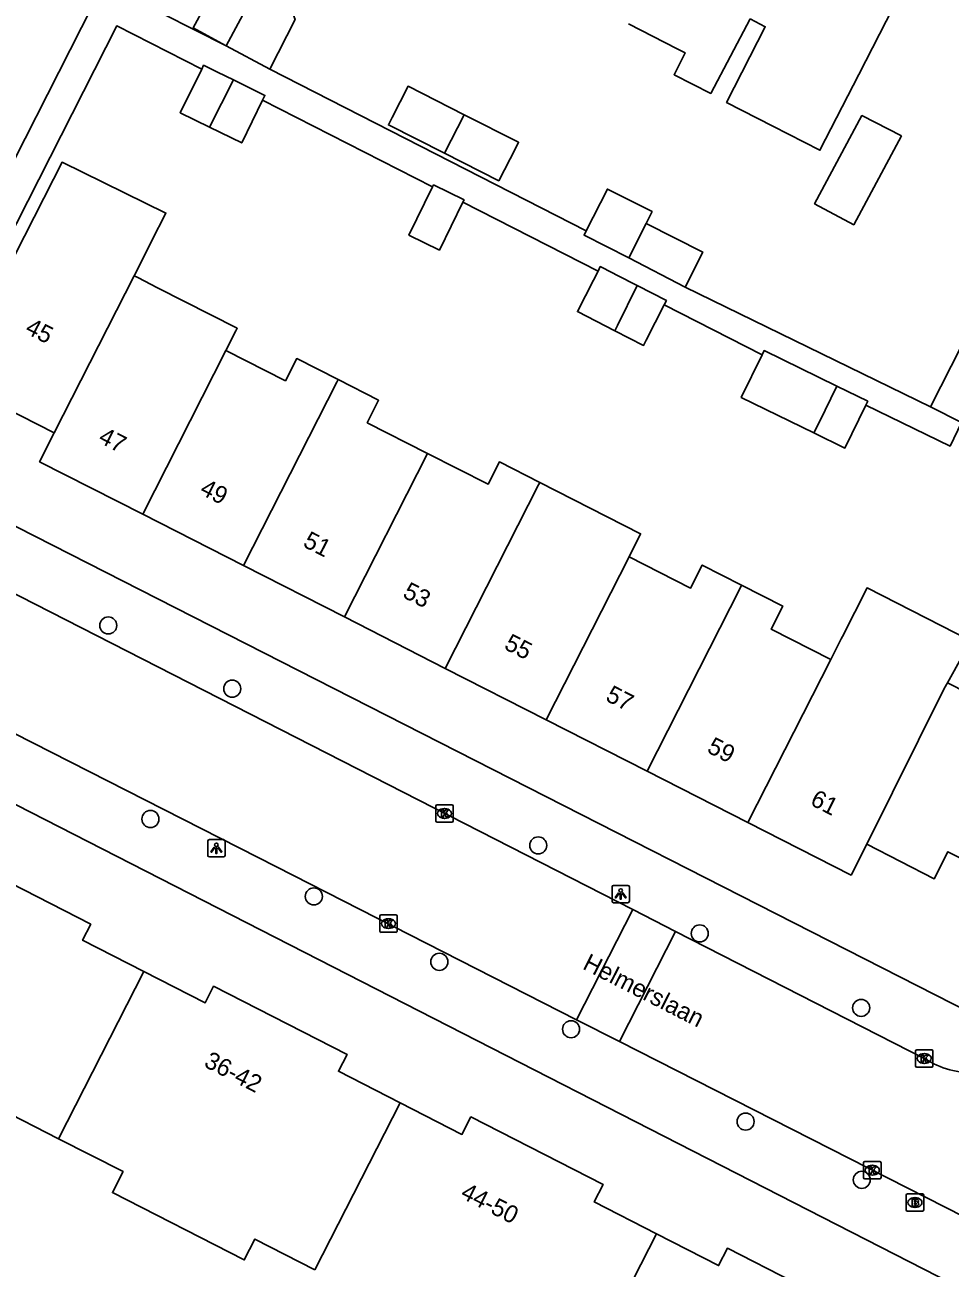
# Model space of a CAD drawing. Extents: x 160356 to 161355, y 381727 to 382845.
# Drawn here: x 161066.7 to 161119.7, y 382327 to 382398.2 of the extents above; entities that cross this region are included whole.
import ezdxf

# ---------------------------------------------------------------- set-up
doc = ezdxf.new("R2010")
doc.units = 0
for name, color, linetype in [('IMGEO_Boom', 7, 'Continuous'), ('IMGEO_Brandkraan', 7, 'Continuous'), ('IMGEO_Kolk', 7, 'Continuous'), ('IMGEO_Lichtpunt', 7, 'Continuous'), ('IMGEO_Openbare_ruimte_label', 7, 'Continuous'), ('IMGEO_Pand', 7, 'Continuous'), ('IMGEO_Pand_nummerreeks', 7, 'Continuous'), ('IMGEO_Rijbaan_lokaal_open', 7, 'Continuous'), ('IMGEO_Voetpad_open', 7, 'Continuous')]:
    doc.layers.add(name, color=color, linetype=linetype)

msp = doc.modelspace()

# ---------------------------------------------------------------- linework, layer by layer
at = {"layer": 'IMGEO_Boom'}
for centre in [(161071.448, 382363.796), (161078.554, 382360.172), (161073.864, 382352.703), (161096.102, 382351.193), (161083.234, 382348.269), (161105.362, 382346.148), (161090.43, 382344.518), (161114.618, 382341.878), (161097.982, 382340.656), (161107.992, 382335.362), (161114.652, 382332.027)]:
    msp.add_circle(centre, 0.489, dxfattribs=at)
at = {"layer": 'IMGEO_Brandkraan'}
for p, q in [((161117.202, 382330.3), (161117.202, 382331.152)), ((161117.277, 382331.226), (161118.129, 382331.226)), ((161117.69, 382331.006), (161117.715, 382331.006)), ((161118.203, 382331.152), (161118.203, 382330.3)), ((161118.129, 382330.226), (161117.277, 382330.226)), ((161117.713, 382330.446), (161117.688, 382330.446))]:
    msp.add_line(p, q, dxfattribs=at)
for points in [[(161117.202, 382330.3), (161117.202, 382331.152)], [(161117.277, 382331.226), (161118.129, 382331.226)], [(161117.55, 382330.926), (161117.55, 382330.526), (161117.763, 382330.526)], [(161117.781, 382330.926), (161117.55, 382330.926)], [(161118.203, 382331.152), (161118.203, 382330.3)], [(161118.129, 382330.226), (161117.277, 382330.226)], [(161117.729, 382330.845), (161117.675, 382330.845), (161117.675, 382330.769)], [(161117.675, 382330.769), (161117.728, 382330.769)], [(161117.737, 382330.693), (161117.675, 382330.693), (161117.675, 382330.612)], [(161117.675, 382330.612), (161117.737, 382330.612)]]:
    msp.add_lwpolyline(points, dxfattribs=at)
for centre, radius, start, end in [((161117.279, 382331.15), 0.0765, 91.55205, 178.44795), ((161117.279, 382331.15), 0.0765, 91.55205, 178.44795), ((161117.785, 382330.781), 0.145, 59.4692, 91.53667), ((161117.81, 382330.828), 0.0922, 285.51372, 58.15012), ((161118.127, 382331.15), 0.0765, 1.55205, 88.44795), ((161118.127, 382331.15), 0.0765, 1.55205, 88.44795), ((161117.279, 382330.302), 0.0765, 181.55205, 268.44795), ((161117.279, 382330.302), 0.0765, 181.55205, 268.44795), ((161117.73, 382330.807), 0.0379, 267.82845, 90.93552), ((161117.738, 382330.652), 0.0404, 269.87594, 90.50774), ((161117.769, 382330.777), 0.251, 268.66757, 293.53466), ((161117.815, 382330.636), 0.105, 301.31148, 78.98903), ((161118.127, 382330.302), 0.0765, 271.55205, 358.44795), ((161118.127, 382330.302), 0.0765, 271.55205, 358.44795)]:
    msp.add_arc(centre, radius, start, end, dxfattribs=at)
for centre, major_axis, ratio, start_param, end_param in [((161117.689, 382330.726), (-0.387, 0.002), 0.722429, 4.712389, 7.853982), ((161117.714, 382330.726), (-0.39, 0.002), 0.717154, 1.570796, 4.712389)]:
    msp.add_ellipse(centre, major_axis=major_axis, ratio=ratio, start_param=start_param, end_param=end_param, dxfattribs=at)
at = {"layer": 'IMGEO_Kolk'}
for p, q in [((161090.226, 382352.596), (161090.226, 382353.448)), ((161090.301, 382353.522), (161091.153, 382353.522)), ((161090.714, 382353.302), (161090.739, 382353.302)), ((161091.227, 382353.448), (161091.227, 382352.596)), ((161091.153, 382352.522), (161090.301, 382352.522)), ((161090.737, 382352.742), (161090.712, 382352.742)), ((161087.012, 382346.284), (161087.012, 382347.136)), ((161087.087, 382347.21), (161087.939, 382347.21)), ((161087.5, 382346.99), (161087.525, 382346.99)), ((161088.013, 382347.136), (161088.013, 382346.284)), ((161087.939, 382346.21), (161087.087, 382346.21)), ((161087.523, 382346.43), (161087.498, 382346.43)), ((161117.808, 382339.478), (161118.66, 382339.478)), ((161117.733, 382338.552), (161117.733, 382339.404)), ((161118.221, 382339.258), (161118.246, 382339.258)), ((161118.734, 382339.404), (161118.734, 382338.552)), ((161118.66, 382338.478), (161117.808, 382338.478)), ((161118.244, 382338.698), (161118.219, 382338.698)), ((161114.83, 382333.078), (161115.682, 382333.078)), ((161114.755, 382332.152), (161114.755, 382333.004)), ((161115.243, 382332.858), (161115.268, 382332.858)), ((161115.756, 382333.004), (161115.756, 382332.152)), ((161115.682, 382332.078), (161114.83, 382332.078)), ((161115.266, 382332.298), (161115.241, 382332.298))]:
    msp.add_line(p, q, dxfattribs=at)
for points in [[(161090.226, 382352.596), (161090.226, 382353.448)], [(161090.301, 382353.522), (161091.153, 382353.522)], [(161090.547, 382353.222), (161090.67, 382353.222), (161090.67, 382353.071), (161090.8, 382353.222), (161090.964, 382353.222), (161090.818, 382353.071), (161090.971, 382352.822), (161090.819, 382352.822), (161090.734, 382352.986), (161090.67, 382352.919), (161090.67, 382352.822), (161090.547, 382352.822), (161090.547, 382353.222)], [(161091.227, 382353.448), (161091.227, 382352.596)], [(161091.153, 382352.522), (161090.301, 382352.522)], [(161087.012, 382346.284), (161087.012, 382347.136)], [(161087.087, 382347.21), (161087.939, 382347.21)], [(161087.333, 382346.91), (161087.456, 382346.91), (161087.456, 382346.759), (161087.586, 382346.91), (161087.75, 382346.91), (161087.604, 382346.759), (161087.757, 382346.51), (161087.605, 382346.51), (161087.52, 382346.674), (161087.456, 382346.607), (161087.456, 382346.51), (161087.333, 382346.51), (161087.333, 382346.91)], [(161088.013, 382347.136), (161088.013, 382346.284)], [(161087.939, 382346.21), (161087.087, 382346.21)], [(161117.808, 382339.478), (161118.66, 382339.478)], [(161117.733, 382338.552), (161117.733, 382339.404)], [(161118.054, 382339.178), (161118.177, 382339.178), (161118.177, 382339.027), (161118.307, 382339.178), (161118.471, 382339.178), (161118.325, 382339.027), (161118.478, 382338.778), (161118.326, 382338.778), (161118.241, 382338.942), (161118.177, 382338.875), (161118.177, 382338.778), (161118.054, 382338.778), (161118.054, 382339.178)], [(161118.734, 382339.404), (161118.734, 382338.552)], [(161118.66, 382338.478), (161117.808, 382338.478)], [(161114.83, 382333.078), (161115.682, 382333.078)], [(161114.755, 382332.152), (161114.755, 382333.004)], [(161115.076, 382332.778), (161115.199, 382332.778), (161115.199, 382332.627), (161115.329, 382332.778), (161115.493, 382332.778), (161115.347, 382332.627), (161115.5, 382332.378), (161115.348, 382332.378), (161115.263, 382332.542), (161115.199, 382332.475), (161115.199, 382332.378), (161115.076, 382332.378), (161115.076, 382332.778)], [(161115.756, 382333.004), (161115.756, 382332.152)], [(161115.682, 382332.078), (161114.83, 382332.078)]]:
    msp.add_lwpolyline(points, dxfattribs=at)
for centre, start, end in [((161090.303, 382353.446), 91.55205, 178.44795), ((161090.303, 382353.446), 91.55205, 178.44795), ((161091.151, 382353.446), 1.55205, 88.44795), ((161091.151, 382353.446), 1.55205, 88.44795), ((161090.303, 382352.598), 181.55205, 268.44795), ((161090.303, 382352.598), 181.55205, 268.44795), ((161091.151, 382352.598), 271.55205, 358.44795), ((161091.151, 382352.598), 271.55205, 358.44795), ((161087.089, 382347.134), 91.55205, 178.44795), ((161087.089, 382347.134), 91.55205, 178.44795), ((161087.937, 382347.134), 1.55205, 88.44795), ((161087.937, 382347.134), 1.55205, 88.44795), ((161087.089, 382346.286), 181.55205, 268.44795), ((161087.089, 382346.286), 181.55205, 268.44795), ((161087.937, 382346.286), 271.55205, 358.44795), ((161087.937, 382346.286), 271.55205, 358.44795), ((161117.81, 382339.402), 91.55205, 178.44795), ((161117.81, 382339.402), 91.55205, 178.44795), ((161118.658, 382339.402), 1.55205, 88.44795), ((161118.658, 382339.402), 1.55205, 88.44795), ((161117.81, 382338.554), 181.55205, 268.44795), ((161117.81, 382338.554), 181.55205, 268.44795), ((161118.658, 382338.554), 271.55205, 358.44795), ((161118.658, 382338.554), 271.55205, 358.44795), ((161114.832, 382333.002), 91.55205, 178.44795), ((161114.832, 382333.002), 91.55205, 178.44795), ((161115.68, 382333.002), 1.55205, 88.44795), ((161115.68, 382333.002), 1.55205, 88.44795), ((161114.832, 382332.154), 181.55205, 268.44795), ((161114.832, 382332.154), 181.55205, 268.44795), ((161115.68, 382332.154), 271.55205, 358.44795), ((161115.68, 382332.154), 271.55205, 358.44795)]:
    msp.add_arc(centre, 0.0765, start, end, dxfattribs=at)
for centre, major_axis, ratio, start_param, end_param in [((161090.713, 382353.022), (-0.387, 0.002), 0.722429, 4.712389, 7.853982), ((161090.738, 382353.022), (-0.39, 0.002), 0.717154, 1.570796, 4.712389), ((161087.499, 382346.71), (-0.387, 0.002), 0.722429, 4.712389, 7.853982), ((161087.524, 382346.71), (-0.39, 0.002), 0.717154, 1.570796, 4.712389), ((161118.22, 382338.978), (-0.387, 0.002), 0.722429, 4.712389, 7.853982), ((161118.245, 382338.978), (-0.39, 0.002), 0.717154, 1.570796, 4.712389), ((161115.242, 382332.578), (-0.387, 0.002), 0.722429, 4.712389, 7.853982), ((161115.267, 382332.578), (-0.39, 0.002), 0.717154, 1.570796, 4.712389)]:
    msp.add_ellipse(centre, major_axis=major_axis, ratio=ratio, start_param=start_param, end_param=end_param, dxfattribs=at)
at = {"layer": 'IMGEO_Lichtpunt'}
for p, q in [((161077.148, 382351.429), (161077.148, 382350.622)), ((161077.148, 382351.429), (161077.148, 382350.622)), ((161078.05, 382351.524), (161077.242, 382351.524)), ((161078.05, 382351.524), (161077.242, 382351.524)), ((161078.144, 382350.622), (161078.144, 382351.429)), ((161078.144, 382350.622), (161078.144, 382351.429)), ((161077.242, 382350.528), (161078.05, 382350.528)), ((161077.242, 382350.528), (161078.05, 382350.528)), ((161100.332, 382348.808), (161100.332, 382348.001)), ((161100.332, 382348.808), (161100.332, 382348.001)), ((161101.234, 382348.903), (161100.426, 382348.903)), ((161101.234, 382348.903), (161100.426, 382348.903)), ((161101.328, 382348.001), (161101.328, 382348.808)), ((161101.328, 382348.001), (161101.328, 382348.808)), ((161100.426, 382347.907), (161101.234, 382347.907)), ((161100.426, 382347.907), (161101.234, 382347.907))]:
    msp.add_line(p, q, dxfattribs=at)
for points in [[(161077.522, 382351.093), (161077.561, 382351.065), (161077.373, 382350.803), (161077.335, 382350.83), (161077.522, 382351.093)], [(161077.624, 382351.045), (161077.671, 382351.045), (161077.671, 382350.723), (161077.624, 382350.723), (161077.624, 382351.045)], [(161077.734, 382351.065), (161077.772, 382351.092), (161077.959, 382350.83), (161077.92, 382350.802), (161077.734, 382351.065)], [(161100.706, 382348.472), (161100.745, 382348.444), (161100.557, 382348.182), (161100.519, 382348.209), (161100.706, 382348.472)], [(161100.808, 382348.424), (161100.855, 382348.424), (161100.855, 382348.102), (161100.808, 382348.102), (161100.808, 382348.424)], [(161100.918, 382348.444), (161100.956, 382348.471), (161101.143, 382348.209), (161101.104, 382348.181), (161100.918, 382348.444)]]:
    msp.add_lwpolyline(points, dxfattribs=at)
for centre in [(161077.647, 382351.227), (161100.831, 382348.606)]:
    msp.add_circle(centre, 0.0994, dxfattribs=at)
for centre, start, end in [((161077.242, 382351.429), 90, 180), ((161077.242, 382351.429), 90, 180), ((161078.05, 382351.429), 0, 90), ((161078.05, 382351.429), 0, 90), ((161077.242, 382350.622), 180, 270), ((161077.242, 382350.622), 180, 270), ((161078.05, 382350.622), 270, 0), ((161078.05, 382350.622), 270, 360), ((161100.426, 382348.808), 90, 180), ((161100.426, 382348.808), 90, 180), ((161101.234, 382348.808), 0, 90), ((161101.234, 382348.808), 0, 90), ((161100.426, 382348.001), 180, 270), ((161100.426, 382348.001), 180, 270), ((161101.234, 382348.001), 270, 0), ((161101.234, 382348.001), 270, 360)]:
    msp.add_arc(centre, 0.0946, start, end, dxfattribs=at)
at = {"layer": 'IMGEO_Pand'}
for points in [[(161117.237, 382400.746), (161114.484, 382395.371), (161112.256, 382391.027), (161109.562, 382392.407), (161106.9, 382393.771), (161109.119, 382398.103), (161108.246, 382398.55)], [(161079.446, 382399.325), (161080.057, 382400.458), (161081.693, 382399.576), (161081.787, 382399.525), (161082.165, 382398.514), (161080.706, 382395.67)], [(161078.203, 382397.019), (161076.318, 382398.035), (161077.027, 382399.349), (161078.591, 382399.786), (161079.446, 382399.325)], [(161078.203, 382397.019), (161079.446, 382399.325)], [(161108.246, 382398.55), (161105.994, 382394.282), (161103.893, 382395.358), (161104.531, 382396.604), (161104.058, 382396.846), (161101.275, 382398.271)], [(161080.706, 382395.67), (161078.203, 382397.019)], [(161076.806, 382395.676), (161076.914, 382395.896), (161077.71, 382395.505), (161078.631, 382395.054)], [(161077.256, 382392.35), (161075.579, 382393.172), (161076.806, 382395.676)], [(161077.256, 382392.35), (161078.631, 382395.054)], [(161078.631, 382395.054), (161080.431, 382394.172), (161080.297, 382393.899)], [(161090.726, 382390.852), (161087.513, 382392.477), (161087.733, 382392.912), (161088.634, 382394.692), (161091.862, 382393.059)], [(161080.297, 382393.899), (161079.097, 382391.448), (161077.256, 382392.35)], [(161091.862, 382393.059), (161094.973, 382391.484), (161094.809, 382391.16), (161093.84, 382389.276), (161090.726, 382390.852)], [(161091.862, 382393.059), (161090.726, 382390.852)], [(161116.927, 382391.856), (161114.193, 382386.759), (161111.95, 382387.963), (161114.662, 382393.018), (161116.927, 382391.856)], [(161068.346, 382374.831), (161064.472, 382376.803), (161065.298, 382378.426), (161063.261, 382379.463), (161065.53, 382383.919), (161068.302, 382389.362), (161068.802, 382390.344), (161074.753, 382387.427), (161073.935, 382385.819), (161073.687, 382385.332), (161072.926, 382383.835)], [(161090.046, 382388.937), (161088.685, 382386.169), (161090.434, 382385.309), (161091.784, 382388.052)], [(161091.784, 382388.052), (161091.848, 382388.183), (161090.099, 382389.044), (161090.046, 382388.937)], [(161102.28, 382386.83), (161102.625, 382387.513), (161100.063, 382388.805), (161098.851, 382386.402)], [(161101.289, 382384.864), (161102.28, 382386.83)], [(161102.28, 382386.83), (161105.536, 382385.188), (161104.527, 382383.189)], [(161098.851, 382386.402), (161098.727, 382386.156), (161101.289, 382384.864)], [(161099.533, 382384.108), (161099.661, 382384.358), (161100.356, 382384.003), (161100.611, 382383.873), (161101.778, 382383.275)], [(161101.289, 382384.864), (161104.527, 382383.189)], [(161072.926, 382383.835), (161068.346, 382374.831)], [(161072.926, 382383.835), (161073.135, 382383.728), (161074.269, 382383.151), (161078.838, 382380.825), (161078.767, 382380.68), (161078.193, 382379.551)], [(161100.495, 382380.684), (161098.344, 382381.784), (161099.267, 382383.587), (161099.533, 382384.108)], [(161101.778, 382383.275), (161100.648, 382380.992), (161100.495, 382380.684)], [(161101.778, 382383.275), (161103.455, 382382.417), (161103.331, 382382.175)], [(161103.331, 382382.175), (161102.294, 382380.149), (161102.137, 382379.843), (161100.495, 382380.684)], [(161118.585, 382376.323), (161121.527, 382382.112), (161122.885, 382381.416), (161123.013, 382381.667), (161123.946, 382381.191), (161124.052, 382381.398), (161124.398, 382381.221)], [(161078.193, 382379.551), (161073.42, 382370.169)], [(161078.193, 382379.551), (161081.602, 382377.815), (161082.25, 382379.088), (161084.621, 382377.881)], [(161108.936, 382379.307), (161109.052, 382379.544), (161113.216, 382377.51)], [(161111.908, 382374.832), (161107.743, 382376.867), (161108.936, 382379.307)], [(161079.203, 382367.225), (161084.551, 382377.738), (161084.621, 382377.881)], [(161084.621, 382377.881), (161086.945, 382376.698), (161086.292, 382375.415), (161089.755, 382373.652)], [(161113.216, 382377.51), (161112.201, 382375.432), (161111.908, 382374.832)], [(161113.216, 382377.51), (161114.994, 382376.641), (161114.89, 382376.429)], [(161114.89, 382376.429), (161113.686, 382373.963), (161111.908, 382374.832)], [(161120.368, 382375.417), (161118.585, 382376.323)], [(161073.42, 382370.169), (161067.505, 382373.18), (161068.346, 382374.831)], [(161089.755, 382373.652), (161084.987, 382364.281)], [(161089.755, 382373.652), (161093.226, 382371.886), (161093.879, 382373.169), (161096.191, 382371.992)], [(161090.771, 382361.337), (161096.121, 382371.852), (161096.191, 382371.992)], [(161096.191, 382371.992), (161101.973, 382369.049), (161101.307, 382367.734)], [(161079.203, 382367.225), (161073.42, 382370.169)], [(161084.987, 382364.281), (161079.203, 382367.225)], [(161096.555, 382358.393), (161101.307, 382367.734)], [(161101.307, 382367.734), (161104.832, 382365.939), (161105.501, 382367.253), (161107.757, 382366.105)], [(161102.339, 382355.448), (161107.69, 382365.967), (161107.757, 382366.105)], [(161107.757, 382366.105), (161110.12, 382364.902), (161109.45, 382363.585), (161112.873, 382361.843)], [(161112.873, 382361.843), (161113.474, 382363.025), (161113.54, 382363.161), (161114.958, 382365.948), (161120.906, 382362.92), (161120.451, 382362.093), (161119.569, 382360.516)], [(161090.771, 382361.337), (161084.987, 382364.281)], [(161108.122, 382352.504), (161112.873, 382361.843)], [(161096.555, 382358.393), (161090.771, 382361.337)], [(161119.569, 382360.516), (161123.148, 382358.695), (161123.966, 382360.303), (161126.327, 382359.101), (161121.596, 382349.807), (161119.596, 382350.825), (161118.809, 382349.28), (161114.934, 382351.253)], [(161119.569, 382360.516), (161119.385, 382360.186), (161114.934, 382351.253)], [(161102.339, 382355.448), (161096.555, 382358.393)], [(161108.122, 382352.504), (161102.339, 382355.448)], [(161114.934, 382351.253), (161114.038, 382349.493), (161108.122, 382352.504)], [(161068.593, 382334.385), (161065.149, 382336.142), (161064.535, 382334.94), (161062.115, 382336.175), (161057.596, 382338.486), (161056.933, 382338.825), (161057.541, 382340.016), (161054.44, 382341.601), (161054.12, 382341.755), (161053.744, 382341.936), (161058.651, 382351.532), (161062.277, 382349.678), (161062.752, 382350.607), (161070.447, 382346.673), (161069.978, 382345.757), (161073.489, 382343.962)], [(161068.593, 382334.385), (161073.489, 382343.962)], [(161073.489, 382343.962), (161076.996, 382342.169), (161077.485, 382343.124), (161085.136, 382339.212), (161084.644, 382338.25), (161088.184, 382336.44)], [(161088.184, 382336.44), (161083.295, 382326.878)], [(161088.184, 382336.44), (161091.726, 382334.629), (161092.24, 382335.635), (161099.818, 382331.761), (161099.309, 382330.765), (161102.878, 382328.94)], [(161083.295, 382326.878), (161079.859, 382328.631), (161079.248, 382327.433), (161071.682, 382331.293), (161072.296, 382332.496), (161068.593, 382334.385)], [(161102.878, 382328.94), (161097.98, 382319.365)], [(161102.878, 382328.94), (161106.443, 382327.117), (161106.95, 382328.108), (161114.553, 382324.221), (161114.06, 382323.258), (161117.678, 382321.409)]]:
    msp.add_lwpolyline(points, dxfattribs=at)
at = {"layer": 'IMGEO_Rijbaan_lokaal_open'}
for points in [[(161101.518, 382347.514), (161083.981, 382356.468), (161025.861, 382386.144)], [(161058.506, 382361.452), (161081.086, 382349.96), (161098.304, 382341.2)], [(161098.304, 382341.2), (161101.518, 382347.514)], [(161101.518, 382347.514), (161103.968, 382346.263)], [(161103.968, 382346.263), (161100.755, 382339.952)], [(161103.968, 382346.263), (161118.275, 382338.958)], [(161100.755, 382339.952), (161098.304, 382341.2)], [(161141.419, 382319.292), (161100.755, 382339.952)]]:
    msp.add_lwpolyline(points, dxfattribs=at)
msp.add_arc((161121.07, 382343.405), 5.253, 237.84959, 271.76481, dxfattribs=at)
at = {"layer": 'IMGEO_Voetpad_open'}
for points in [[(161078.475, 382410.98), (161072.767, 382399.786), (161078.203, 382397.019)], [(161057.577, 382373.824), (161070.563, 382399.333), (161050.65, 382409.432)], [(161076.806, 382395.676), (161071.937, 382398.155), (161059.146, 382373.026)], [(161080.706, 382395.67), (161098.851, 382386.402)], [(161090.046, 382388.937), (161080.297, 382393.899)], [(161099.533, 382384.108), (161091.784, 382388.052)], [(161104.527, 382383.189), (161118.585, 382376.323)], [(161108.936, 382379.307), (161103.331, 382382.175)], [(161120.368, 382375.417), (161119.712, 382374.074), (161114.89, 382376.429)], [(161059.146, 382373.026), (161085.402, 382359.661), (161120.886, 382341.599)], [(161138.843, 382316.361), (161057.073, 382358.164)]]:
    msp.add_lwpolyline(points, dxfattribs=at)

# ---------------------------------------------------------------- texts
at = {"layer": 'IMGEO_Openbare_ruimte_label'}
msp.add_text('Helmerslaan', height=1, rotation=332.99935, dxfattribs=at).set_placement((161098.587, 382344.143))
at = {"layer": 'IMGEO_Pand_nummerreeks'}
for s, rotation, p in [('45', 333.01942, (161066.623, 382380.578)), ('47', 333.01942, (161070.82, 382374.32)), ('49', 333.01942, (161076.637, 382371.359)), ('51', 333.01942, (161082.554, 382368.347)), ('53', 333.01942, (161088.27, 382365.437)), ('55', 333.01942, (161094.086, 382362.476)), ('57', 333.01942, (161099.903, 382359.516)), ('59', 333.01942, (161105.72, 382356.555)), ('61', 333.01942, (161111.637, 382353.543)), ('36-42', 332.87045, (161076.875, 382338.545)), ('44-50', 332.9965, (161091.585, 382331.02))]:
    msp.add_text(s, height=1, rotation=rotation, dxfattribs=at).set_placement(p)

doc.saveas('drawing.dxf')
